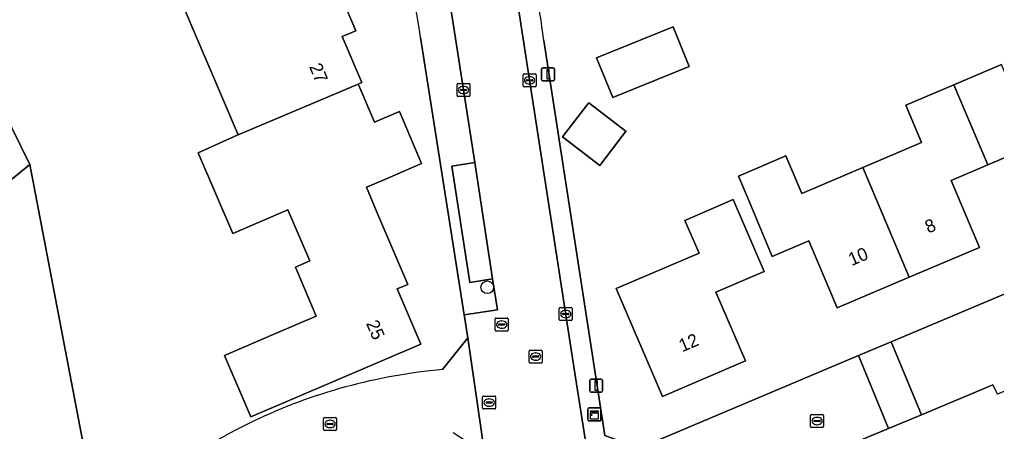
# Model space of a CAD drawing. Extents: x 158472 to 159562, y 388525 to 389606.
# Drawn here: x 158526.8 to 158602.1, y 389028 to 389059.8 of the extents above; entities that cross this region are included whole.
import ezdxf

# ---------------------------------------------------------------- set-up
doc = ezdxf.new("R2010")
doc.units = 0
for name, color, linetype in [('IMGEO_Boom', 7, 'Continuous'), ('IMGEO_Brandkraan', 7, 'Continuous'), ('IMGEO_Erf', 7, 'Continuous'), ('IMGEO_Greppel_droge_sloot', 7, 'Continuous'), ('IMGEO_Groenvoorziening', 7, 'Continuous'), ('IMGEO_Hek', 7, 'Continuous'), ('IMGEO_Kast', 7, 'Continuous'), ('IMGEO_Kolk', 7, 'Continuous'), ('IMGEO_Lichtmast', 7, 'Continuous'), ('IMGEO_Muur', 7, 'Continuous'), ('IMGEO_Pand', 7, 'Continuous'), ('IMGEO_Pand_nummerreeks', 7, 'Continuous'), ('IMGEO_Parkeervlak_open', 7, 'Continuous'), ('IMGEO_Rijbaan_lokaal_open', 7, 'Continuous'), ('IMGEO_Rioolput', 7, 'Continuous'), ('IMGEO_Voetpad_open', 7, 'Continuous')]:
    doc.layers.add(name, color=color, linetype=linetype)

msp = doc.modelspace()

# ---------------------------------------------------------------- linework, layer by layer
at = {"layer": 'IMGEO_Boom'}
msp.add_circle((158562.844, 389039.142), 0.489, dxfattribs=at)
at = {"layer": 'IMGEO_Brandkraan'}
for p, q in [((158562.492, 389029.828), (158562.492, 389030.68)), ((158562.567, 389030.754), (158563.419, 389030.754)), ((158562.751, 389030.248), (158562.751, 389030.26)), ((158563.189, 389030.211), (158562.791, 389030.211)), ((158562.794, 389030.297), (158563.192, 389030.297)), ((158562.98, 389030.534), (158563.005, 389030.534)), ((158563.235, 389030.26), (158563.235, 389030.248)), ((158563.493, 389030.68), (158563.493, 389029.828)), ((158563.419, 389029.754), (158562.567, 389029.754)), ((158563.003, 389029.974), (158562.978, 389029.974))]:
    msp.add_line(p, q, dxfattribs=at)
for points in [[(158562.492, 389029.828), (158562.492, 389030.68)], [(158562.567, 389030.754), (158563.419, 389030.754)], [(158563.493, 389030.68), (158563.493, 389029.828)], [(158563.419, 389029.754), (158562.567, 389029.754)]]:
    msp.add_lwpolyline(points, dxfattribs=at)
for centre, radius, start, end in [((158562.569, 389030.678), 0.0765, 91.55205, 178.44795), ((158562.569, 389030.678), 0.0765, 91.55205, 178.44795), ((158562.791, 389030.257), 0.0403, 85.87752, 175.75265), ((158562.788, 389030.247), 0.0366, 178.93798, 274.71019), ((158563.192, 389030.254), 0.043, 264.86636, 352.45326), ((158563.196, 389030.259), 0.0386, 1.73085, 96.63898), ((158563.417, 389030.678), 0.0765, 1.55205, 88.44795), ((158563.417, 389030.678), 0.0765, 1.55205, 88.44795), ((158562.569, 389029.83), 0.0765, 181.55205, 268.44795), ((158562.569, 389029.83), 0.0765, 181.55205, 268.44795), ((158563.417, 389029.83), 0.0765, 271.55205, 358.44795), ((158563.417, 389029.83), 0.0765, 271.55205, 358.44795)]:
    msp.add_arc(centre, radius, start, end, dxfattribs=at)
for centre, major_axis, ratio, start_param, end_param in [((158562.979, 389030.254), (-0.387, 0.002), 0.722429, 4.712389, 7.853982), ((158563.004, 389030.254), (-0.39, 0.002), 0.717154, 1.570796, 4.712389)]:
    msp.add_ellipse(centre, major_axis=major_axis, ratio=ratio, start_param=start_param, end_param=end_param, dxfattribs=at)
at = {"layer": 'IMGEO_Erf'}
for points in [[(158502.141, 389112.903), (158501.952, 389108.465), (158502.035, 389106.941), (158502.367, 389105.452), (158514.242, 389075.687), (158527.566, 389048.61), (158531.766, 389026.678), (158531.912, 389026.815), (158535.634, 389022.859)], [(158567.204, 389058.167), (158571.923, 389027.713), (158574.563, 389026.742), (158591.467, 389033.868), (158594.001, 389034.936), (158639.056, 389053.929), (158636.872, 389059.257), (158632.833, 389069.111), (158631.513, 389072.331), (158629.191, 389077.996), (158628.001, 389080.824), (158631.763, 389082.407), (158632.597, 389082.746), (158633.427, 389083.084), (158632.28, 389085.631)], [(158549.925, 389065.446), (158552.722, 389058.914), (158551.668, 389058.463), (158553.183, 389054.923), (158552.9, 389054.803), (158552.95, 389054.687), (158554.162, 389051.857), (158556.07, 389052.675), (158557.787, 389048.667), (158554.94, 389047.448), (158553.526, 389046.842), (158554.342, 389044.936), (158556.73, 389039.361), (158555.91, 389039.01), (158557.73, 389034.76), (158544.614, 389029.143), (158542.583, 389033.884), (158546.521, 389035.571), (158549.66, 389036.915), (158548.045, 389040.687), (158549.165, 389041.167), (158547.473, 389045.119), (158543.214, 389043.295), (158540.555, 389049.505), (158543.564, 389050.852), (158543.635, 389050.882), (158539.341, 389060.935)], [(158559.407, 389032.787), (158561.354, 389035.245), (158561.076, 389037.004), (158557.702, 389058.383)], [(158695.038, 389031.866), (158693.979, 389034.415), (158691.297, 389040.872), (158689.958, 389044.098), (158688.082, 389043.319), (158668.118, 389058.458), (158641.722, 389047.425), (158602.187, 389030.899), (158601.851, 389031.612), (158596.34, 389029.317), (158593.802, 389028.26), (158586.677, 389025.294), (158575.064, 389020.458), (158573.349, 389019.024)], [(158604.191, 389049.721), (158601.463, 389048.565), (158598.623, 389047.362), (158600.808, 389042.206), (158595.387, 389039.909), (158589.835, 389037.557), (158587.649, 389042.716), (158584.833, 389041.522), (158582.882, 389046.126), (158582.213, 389047.706), (158585.879, 389049.26), (158587.102, 389046.373), (158591.805, 389048.365), (158596.345, 389050.288), (158595.122, 389053.174), (158598.842, 389054.75), (158602.499, 389056.3)]]:
    msp.add_lwpolyline(points, dxfattribs=at)
for points in [[(158571.283, 389056.835), (158577.19, 389059.217), (158578.429, 389056.144), (158572.522, 389053.762)], [(158573.551, 389051.157), (158573.495, 389051.084), (158571.532, 389048.518), (158568.652, 389050.721), (158570.549, 389053.202), (158570.67, 389053.36)], [(158584.194, 389040.362), (158580.476, 389038.767), (158582.751, 389033.466), (158576.363, 389030.724), (158572.797, 389039.033), (158579.179, 389041.772), (158578.097, 389044.293), (158581.821, 389045.891)]]:
    msp.add_lwpolyline(points, close=True, dxfattribs=at)
for centre, radius, start, end in [((158505.178, 389050.505), 62.498, 7.04204, 22.44265), ((158505.258, 389050.935), 52.97, 8.08322, 18.56797), ((158563.031, 388990.674), 42.269, 94.91889, 115.60393), ((158563.038, 388990.677), 42.269, 115.6136, 130.41517)]:
    msp.add_arc(centre, radius, start, end, dxfattribs=at)
at = {"layer": 'IMGEO_Greppel_droge_sloot'}
msp.add_lwpolyline([(158513.442, 389071.069), (158525.906, 389047.243), (158527.566, 389048.61), (158514.242, 389075.687), (158502.367, 389105.452), (158502.035, 389106.941), (158501.952, 389108.465)], dxfattribs=at)
at = {"layer": 'IMGEO_Groenvoorziening'}
msp.add_lwpolyline([(158527.566, 389048.61), (158525.906, 389047.243), (158510.767, 389041.228), (158507.796, 389039.907), (158521.964, 389021.036), (158524.844, 389017.393), (158526.575, 389013.829), (158529.563, 389016.942), (158530.165, 389017.568), (158531.838, 389019.257), (158535.49, 389022.722), (158531.766, 389026.678)], close=True, dxfattribs=at)
at = {"layer": 'IMGEO_Hek'}
msp.add_lwpolyline([(158527.566, 389048.61), (158531.766, 389026.678)], dxfattribs=at)
at = {"layer": 'IMGEO_Kast'}
for p, q in [((158570.614, 389028.908), (158570.614, 389029.749)), ((158570.614, 389029.749), (158570.614, 389028.908)), ((158570.689, 389029.833), (158571.53, 389029.833)), ((158571.53, 389029.833), (158570.689, 389029.833)), ((158571.614, 389029.758), (158571.614, 389028.917)), ((158571.614, 389028.917), (158571.614, 389029.758)), ((158571.539, 389028.833), (158570.698, 389028.833)), ((158570.698, 389028.833), (158571.539, 389028.833))]:
    msp.add_line(p, q, dxfattribs=at)
for points in [[(158570.809, 389029.623), (158571.409, 389029.623), (158571.409, 389029.538), (158570.809, 389029.538), (158570.809, 389029.623)], [(158570.809, 389029.448), (158571.409, 389029.448), (158571.409, 389028.959), (158570.809, 389028.959), (158570.809, 389029.448)]]:
    msp.add_lwpolyline(points, dxfattribs=at)
msp.add_circle((158570.893, 389029.297), 0.0377, dxfattribs=at)
for centre, start, end in [((158570.692, 389029.755), 92.4484, 184.28452), ((158570.692, 389029.755), 92.4484, 184.28452), ((158571.536, 389029.755), 2.4484, 94.28452), ((158571.536, 389029.755), 2.4484, 94.28452), ((158570.692, 389028.911), 182.4484, 274.28452), ((158570.692, 389028.911), 182.4484, 274.28452), ((158571.536, 389028.911), 272.4484, 4.28452), ((158571.536, 389028.911), 272.4484, 4.28452)]:
    msp.add_arc(centre, 0.0779, start, end, dxfattribs=at)
at = {"layer": 'IMGEO_Kolk'}
for p, q in [((158565.613, 389054.668), (158565.613, 389055.52)), ((158565.688, 389055.594), (158566.54, 389055.594)), ((158565.872, 389055.088), (158565.872, 389055.1)), ((158566.31, 389055.051), (158565.912, 389055.051)), ((158565.915, 389055.137), (158566.313, 389055.137)), ((158566.101, 389055.374), (158566.126, 389055.374)), ((158566.356, 389055.1), (158566.356, 389055.088)), ((158566.614, 389055.52), (158566.614, 389054.668)), ((158560.514, 389053.916), (158560.514, 389054.768)), ((158560.589, 389054.842), (158561.441, 389054.842)), ((158560.773, 389054.336), (158560.773, 389054.348)), ((158561.211, 389054.299), (158560.813, 389054.299)), ((158560.816, 389054.385), (158561.214, 389054.385)), ((158561.002, 389054.622), (158561.027, 389054.622)), ((158561.257, 389054.348), (158561.257, 389054.336)), ((158561.515, 389054.768), (158561.515, 389053.916)), ((158566.54, 389054.594), (158565.688, 389054.594)), ((158566.124, 389054.814), (158566.099, 389054.814)), ((158561.441, 389053.842), (158560.589, 389053.842)), ((158561.025, 389054.062), (158561, 389054.062)), ((158568.401, 389036.646), (158568.401, 389037.498)), ((158568.476, 389037.572), (158569.328, 389037.572)), ((158568.66, 389037.066), (158568.66, 389037.078)), ((158569.098, 389037.029), (158568.7, 389037.029)), ((158568.703, 389037.115), (158569.101, 389037.115)), ((158568.889, 389037.352), (158568.914, 389037.352)), ((158569.144, 389037.078), (158569.144, 389037.066)), ((158569.402, 389037.498), (158569.402, 389036.646)), ((158563.459, 389035.839), (158563.459, 389036.691)), ((158563.534, 389036.765), (158564.386, 389036.765)), ((158563.718, 389036.259), (158563.718, 389036.271)), ((158564.156, 389036.222), (158563.758, 389036.222)), ((158563.761, 389036.308), (158564.159, 389036.308)), ((158563.947, 389036.545), (158563.972, 389036.545)), ((158564.202, 389036.271), (158564.202, 389036.259)), ((158564.46, 389036.691), (158564.46, 389035.839)), ((158569.328, 389036.572), (158568.476, 389036.572)), ((158568.912, 389036.792), (158568.887, 389036.792)), ((158564.386, 389035.765), (158563.534, 389035.765)), ((158563.97, 389035.985), (158563.945, 389035.985)), ((158587.861, 389029.323), (158588.713, 389029.323)), ((158550.223, 389028.179), (158550.223, 389029.031)), ((158550.298, 389029.105), (158551.15, 389029.105)), ((158550.482, 389028.599), (158550.482, 389028.611)), ((158550.525, 389028.648), (158550.923, 389028.648)), ((158550.711, 389028.885), (158550.736, 389028.885)), ((158550.966, 389028.611), (158550.966, 389028.599)), ((158551.224, 389029.031), (158551.224, 389028.179)), ((158587.786, 389028.397), (158587.786, 389029.249)), ((158588.045, 389028.817), (158588.045, 389028.829)), ((158588.483, 389028.78), (158588.085, 389028.78)), ((158588.088, 389028.866), (158588.486, 389028.866)), ((158588.274, 389029.103), (158588.299, 389029.103)), ((158588.529, 389028.829), (158588.529, 389028.817)), ((158588.787, 389029.249), (158588.787, 389028.397)), ((158551.15, 389028.105), (158550.298, 389028.105)), ((158550.92, 389028.562), (158550.522, 389028.562)), ((158550.734, 389028.325), (158550.709, 389028.325)), ((158588.713, 389028.323), (158587.861, 389028.323)), ((158588.297, 389028.543), (158588.272, 389028.543))]:
    msp.add_line(p, q, dxfattribs=at)
for points in [[(158565.613, 389054.668), (158565.613, 389055.52)], [(158565.688, 389055.594), (158566.54, 389055.594)], [(158566.614, 389055.52), (158566.614, 389054.668)], [(158560.514, 389053.916), (158560.514, 389054.768)], [(158560.589, 389054.842), (158561.441, 389054.842)], [(158561.515, 389054.768), (158561.515, 389053.916)], [(158566.54, 389054.594), (158565.688, 389054.594)], [(158561.441, 389053.842), (158560.589, 389053.842)], [(158568.401, 389036.646), (158568.401, 389037.498)], [(158568.476, 389037.572), (158569.328, 389037.572)], [(158569.402, 389037.498), (158569.402, 389036.646)], [(158563.459, 389035.839), (158563.459, 389036.691)], [(158563.534, 389036.765), (158564.386, 389036.765)], [(158564.46, 389036.691), (158564.46, 389035.839)], [(158569.328, 389036.572), (158568.476, 389036.572)], [(158564.386, 389035.765), (158563.534, 389035.765)], [(158587.861, 389029.323), (158588.713, 389029.323)], [(158550.223, 389028.179), (158550.223, 389029.031)], [(158550.298, 389029.105), (158551.15, 389029.105)], [(158551.224, 389029.031), (158551.224, 389028.179)], [(158587.786, 389028.397), (158587.786, 389029.249)], [(158588.787, 389029.249), (158588.787, 389028.397)], [(158551.15, 389028.105), (158550.298, 389028.105)], [(158588.713, 389028.323), (158587.861, 389028.323)]]:
    msp.add_lwpolyline(points, dxfattribs=at)
for centre, radius, start, end in [((158565.69, 389055.518), 0.0765, 91.55205, 178.44795), ((158565.69, 389055.518), 0.0765, 91.55205, 178.44795), ((158565.912, 389055.097), 0.0403, 85.87752, 175.75265), ((158565.909, 389055.087), 0.0366, 178.93798, 274.71019), ((158566.313, 389055.094), 0.043, 264.86636, 352.45326), ((158566.317, 389055.099), 0.0386, 1.73085, 96.63898), ((158566.538, 389055.518), 0.0765, 1.55205, 88.44795), ((158566.538, 389055.518), 0.0765, 1.55205, 88.44795), ((158560.591, 389054.766), 0.0765, 91.55205, 178.44795), ((158560.591, 389054.766), 0.0765, 91.55205, 178.44795), ((158560.813, 389054.345), 0.0403, 85.87752, 175.75265), ((158560.81, 389054.335), 0.0366, 178.93798, 274.71019), ((158561.214, 389054.342), 0.043, 264.86636, 352.45326), ((158561.218, 389054.347), 0.0386, 1.73085, 96.63898), ((158561.439, 389054.766), 0.0765, 1.55205, 88.44795), ((158561.439, 389054.766), 0.0765, 1.55205, 88.44795), ((158565.69, 389054.67), 0.0765, 181.55205, 268.44795), ((158565.69, 389054.67), 0.0765, 181.55205, 268.44795), ((158566.538, 389054.67), 0.0765, 271.55205, 358.44795), ((158566.538, 389054.67), 0.0765, 271.55205, 358.44795), ((158560.591, 389053.918), 0.0765, 181.55205, 268.44795), ((158560.591, 389053.918), 0.0765, 181.55205, 268.44795), ((158561.439, 389053.918), 0.0765, 271.55205, 358.44795), ((158561.439, 389053.918), 0.0765, 271.55205, 358.44795), ((158568.478, 389037.496), 0.0765, 91.55205, 178.44795), ((158568.478, 389037.496), 0.0765, 91.55205, 178.44795), ((158568.7, 389037.075), 0.0403, 85.87752, 175.75265), ((158568.697, 389037.065), 0.0366, 178.93798, 274.71019), ((158569.101, 389037.072), 0.043, 264.86636, 352.45326), ((158569.105, 389037.077), 0.0386, 1.73085, 96.63898), ((158569.326, 389037.496), 0.0765, 1.55205, 88.44795), ((158569.326, 389037.496), 0.0765, 1.55205, 88.44795), ((158563.536, 389036.689), 0.0765, 91.55205, 178.44795), ((158563.536, 389036.689), 0.0765, 91.55205, 178.44795), ((158563.758, 389036.268), 0.0403, 85.87752, 175.75265), ((158563.755, 389036.258), 0.0366, 178.93798, 274.71019), ((158564.159, 389036.265), 0.043, 264.86636, 352.45326), ((158564.163, 389036.27), 0.0386, 1.73085, 96.63898), ((158564.384, 389036.689), 0.0765, 1.55205, 88.44795), ((158564.384, 389036.689), 0.0765, 1.55205, 88.44795), ((158568.478, 389036.648), 0.0765, 181.55205, 268.44795), ((158568.478, 389036.648), 0.0765, 181.55205, 268.44795), ((158569.326, 389036.648), 0.0765, 271.55205, 358.44795), ((158569.326, 389036.648), 0.0765, 271.55205, 358.44795), ((158563.536, 389035.841), 0.0765, 181.55205, 268.44795), ((158563.536, 389035.841), 0.0765, 181.55205, 268.44795), ((158564.384, 389035.841), 0.0765, 271.55205, 358.44795), ((158564.384, 389035.841), 0.0765, 271.55205, 358.44795), ((158587.863, 389029.247), 0.0765, 91.55205, 178.44795), ((158587.863, 389029.247), 0.0765, 91.55205, 178.44795), ((158588.711, 389029.247), 0.0765, 1.55205, 88.44795), ((158588.711, 389029.247), 0.0765, 1.55205, 88.44795), ((158550.3, 389029.029), 0.0765, 91.55205, 178.44795), ((158550.3, 389029.029), 0.0765, 91.55205, 178.44795), ((158550.522, 389028.608), 0.0403, 85.87752, 175.75265), ((158550.519, 389028.598), 0.0366, 178.93798, 274.71019), ((158550.923, 389028.605), 0.043, 264.86636, 352.45326), ((158550.927, 389028.61), 0.0386, 1.73085, 96.63898), ((158551.148, 389029.029), 0.0765, 1.55205, 88.44795), ((158551.148, 389029.029), 0.0765, 1.55205, 88.44795), ((158588.085, 389028.826), 0.0403, 85.87752, 175.75265), ((158588.082, 389028.816), 0.0366, 178.93798, 274.71019), ((158588.486, 389028.823), 0.043, 264.86636, 352.45326), ((158588.49, 389028.828), 0.0386, 1.73085, 96.63898), ((158550.3, 389028.181), 0.0765, 181.55205, 268.44795), ((158550.3, 389028.181), 0.0765, 181.55205, 268.44795), ((158551.148, 389028.181), 0.0765, 271.55205, 358.44795), ((158551.148, 389028.181), 0.0765, 271.55205, 358.44795), ((158587.863, 389028.399), 0.0765, 181.55205, 268.44795), ((158587.863, 389028.399), 0.0765, 181.55205, 268.44795), ((158588.711, 389028.399), 0.0765, 271.55205, 358.44795), ((158588.711, 389028.399), 0.0765, 271.55205, 358.44795)]:
    msp.add_arc(centre, radius, start, end, dxfattribs=at)
for centre, major_axis, ratio, start_param, end_param in [((158566.1, 389055.094), (-0.387, 0.002), 0.722429, 4.712389, 7.853982), ((158566.125, 389055.094), (-0.39, 0.002), 0.717154, 1.570796, 4.712389), ((158561.001, 389054.342), (-0.387, 0.002), 0.722429, 4.712389, 7.853982), ((158561.026, 389054.342), (-0.39, 0.002), 0.717154, 1.570796, 4.712389), ((158568.888, 389037.072), (-0.387, 0.002), 0.722429, 4.712389, 7.853982), ((158568.913, 389037.072), (-0.39, 0.002), 0.717154, 1.570796, 4.712389), ((158563.946, 389036.265), (-0.387, 0.002), 0.722429, 4.712389, 7.853982), ((158563.971, 389036.265), (-0.39, 0.002), 0.717154, 1.570796, 4.712389), ((158550.71, 389028.605), (-0.387, 0.002), 0.722429, 4.712389, 7.853982), ((158550.735, 389028.605), (-0.39, 0.002), 0.717154, 1.570796, 4.712389), ((158588.273, 389028.823), (-0.387, 0.002), 0.722429, 4.712389, 7.853982), ((158588.298, 389028.823), (-0.39, 0.002), 0.717154, 1.570796, 4.712389)]:
    msp.add_ellipse(centre, major_axis=major_axis, ratio=ratio, start_param=start_param, end_param=end_param, dxfattribs=at)
at = {"layer": 'IMGEO_Lichtmast'}
for p, q in [((158567.036, 389055.154), (158567.036, 389055.954)), ((158567.036, 389055.954), (158567.036, 389055.154)), ((158567.136, 389056.054), (158567.926, 389056.054)), ((158567.926, 389056.054), (158567.136, 389056.054)), ((158568.026, 389055.954), (158568.026, 389055.154)), ((158568.026, 389055.154), (158568.026, 389055.954)), ((158567.926, 389055.054), (158567.136, 389055.054)), ((158567.136, 389055.054), (158567.926, 389055.054)), ((158570.753, 389031.164), (158570.753, 389031.964)), ((158570.753, 389031.964), (158570.753, 389031.164)), ((158570.853, 389032.064), (158571.643, 389032.064)), ((158571.643, 389032.064), (158570.853, 389032.064)), ((158571.743, 389031.964), (158571.743, 389031.164)), ((158571.743, 389031.164), (158571.743, 389031.964)), ((158571.643, 389031.064), (158570.853, 389031.064)), ((158570.853, 389031.064), (158571.643, 389031.064))]:
    msp.add_line(p, q, dxfattribs=at)
for points in [[(158567.456, 389055.929), (158567.606, 389055.929), (158567.606, 389055.179), (158567.456, 389055.179), (158567.456, 389055.929)], [(158571.173, 389031.939), (158571.323, 389031.939), (158571.323, 389031.189), (158571.173, 389031.189), (158571.173, 389031.939)]]:
    msp.add_lwpolyline(points, dxfattribs=at)
for centre, start, end in [((158567.136, 389055.954), 90, 180), ((158567.136, 389055.954), 90, 180), ((158567.926, 389055.954), 0, 90), ((158567.926, 389055.954), 360, 90), ((158567.136, 389055.154), 180, 270), ((158567.136, 389055.154), 180, 270), ((158567.926, 389055.154), 270, 0), ((158567.926, 389055.154), 270, 0), ((158570.853, 389031.964), 90, 180), ((158570.853, 389031.964), 90, 180), ((158571.643, 389031.964), 0, 90), ((158571.643, 389031.964), 360, 90), ((158570.853, 389031.164), 180, 270), ((158570.853, 389031.164), 180, 270), ((158571.643, 389031.164), 270, 0), ((158571.643, 389031.164), 270, 0)]:
    msp.add_arc(centre, 0.1, start, end, dxfattribs=at)
at = {"layer": 'IMGEO_Muur'}
for points in [[(158601.851, 389031.612), (158596.34, 389029.317)], [(158596.34, 389029.317), (158593.802, 389028.26)], [(158593.802, 389028.26), (158586.677, 389025.294)]]:
    msp.add_lwpolyline(points, dxfattribs=at)
msp.add_arc((158563.038, 388990.677), 42.269, 115.6136, 130.41517, dxfattribs=at)
at = {"layer": 'IMGEO_Pand'}
for points in [[(158549.925, 389065.446), (158542.488, 389062.32), (158539.341, 389060.935), (158543.635, 389050.882), (158552.9, 389054.803), (158553.183, 389054.923), (158551.668, 389058.463), (158552.722, 389058.914)], [(158571.283, 389056.835), (158572.522, 389053.762), (158578.429, 389056.144), (158577.19, 389059.217)], [(158608.356, 389055.289), (158603.753, 389053.339), (158602.499, 389056.3), (158598.842, 389054.75), (158601.463, 389048.565), (158604.191, 389049.721), (158606.375, 389044.567), (158611.905, 389046.91)], [(158552.9, 389054.803), (158543.635, 389050.882), (158543.564, 389050.852), (158540.555, 389049.505), (158543.214, 389043.295), (158547.473, 389045.119), (158549.165, 389041.167), (158548.045, 389040.687), (158549.66, 389036.915), (158546.521, 389035.571), (158542.583, 389033.884), (158544.614, 389029.143), (158557.73, 389034.76), (158555.91, 389039.01), (158556.73, 389039.361), (158554.342, 389044.936), (158553.526, 389046.842), (158554.94, 389047.448), (158557.787, 389048.667), (158556.07, 389052.675), (158554.162, 389051.857), (158552.95, 389054.687)], [(158591.805, 389048.365), (158595.387, 389039.909), (158600.808, 389042.206), (158598.623, 389047.362), (158601.463, 389048.565), (158598.842, 389054.75), (158595.122, 389053.174), (158596.345, 389050.288)], [(158570.549, 389053.202), (158568.652, 389050.721), (158571.532, 389048.518), (158573.495, 389051.084), (158573.551, 389051.157), (158570.67, 389053.36)], [(158591.805, 389048.365), (158587.102, 389046.373), (158585.879, 389049.26), (158582.213, 389047.706), (158582.882, 389046.126), (158584.833, 389041.522), (158587.649, 389042.716), (158589.835, 389037.557), (158595.387, 389039.909)], [(158576.363, 389030.724), (158582.751, 389033.466), (158580.476, 389038.767), (158584.194, 389040.362), (158581.821, 389045.891), (158578.097, 389044.293), (158579.179, 389041.772), (158572.797, 389039.033)]]:
    msp.add_lwpolyline(points, close=True, dxfattribs=at)
at = {"layer": 'IMGEO_Parkeervlak_open'}
msp.add_lwpolyline([(158561.894, 389048.745), (158560.106, 389048.467), (158561.494, 389039.516), (158563.263, 389039.779)], close=True, dxfattribs=at)
at = {"layer": 'IMGEO_Rijbaan_lokaal_open'}
for points in [[(158559.452, 389063.776), (158559.84, 389061.953), (158561.894, 389048.745), (158563.263, 389039.779), (158563.629, 389037.407), (158561.076, 389037.004), (158561.354, 389035.245), (158562.628, 389026.376), (158562.866, 389024.858), (158564.862, 389025.171), (158565.571, 389024.773), (158565.711, 389023.893), (158566.45, 389019.648), (158566.603, 389019.063), (158566.791, 389018.156)], [(158569.658, 389032.192), (158564.949, 389062.628)], [(158564.949, 389062.628), (158569.658, 389032.192), (158571.227, 389022.248)], [(158571.923, 389027.713), (158567.204, 389058.167)], [(158639.056, 389053.929), (158594.001, 389034.936), (158596.34, 389029.317), (158601.851, 389031.612), (158602.187, 389030.899)], [(158560.226, 389027.942), (158562.628, 389026.376), (158561.354, 389035.245), (158559.407, 389032.787)], [(158573.349, 389019.024), (158575.064, 389020.458), (158586.677, 389025.294), (158593.802, 389028.26), (158591.467, 389033.868), (158574.563, 389026.742), (158571.923, 389027.713)], [(158571.227, 389022.248), (158569.658, 389032.192)]]:
    msp.add_lwpolyline(points, dxfattribs=at)
msp.add_lwpolyline([(158596.34, 389029.317), (158594.001, 389034.936), (158591.467, 389033.868), (158593.802, 389028.26)], close=True, dxfattribs=at)
for centre, radius, start, end in [((158505.178, 389050.505), 62.498, 7.04204, 22.44265), ((158563.031, 388990.674), 42.269, 94.91889, 115.60393), ((158563.038, 388990.677), 42.269, 115.6136, 130.41517)]:
    msp.add_arc(centre, radius, start, end, dxfattribs=at)
at = {"layer": 'IMGEO_Rioolput'}
for p, q in [((158566.076, 389033.372), (158566.076, 389034.224)), ((158566.151, 389034.298), (158567.003, 389034.298)), ((158566.378, 389033.841), (158566.776, 389033.841)), ((158566.564, 389034.078), (158566.589, 389034.078)), ((158567.077, 389034.224), (158567.077, 389033.372)), ((158567.003, 389033.298), (158566.151, 389033.298)), ((158566.335, 389033.792), (158566.335, 389033.804)), ((158566.773, 389033.755), (158566.375, 389033.755)), ((158566.587, 389033.518), (158566.562, 389033.518)), ((158566.819, 389033.804), (158566.819, 389033.792))]:
    msp.add_line(p, q, dxfattribs=at)
for points in [[(158566.076, 389033.372), (158566.076, 389034.224)], [(158566.151, 389034.298), (158567.003, 389034.298)], [(158567.077, 389034.224), (158567.077, 389033.372)], [(158567.003, 389033.298), (158566.151, 389033.298)]]:
    msp.add_lwpolyline(points, dxfattribs=at)
for centre, radius, start, end in [((158566.153, 389034.222), 0.0765, 91.55205, 178.44795), ((158566.153, 389034.222), 0.0765, 91.55205, 178.44795), ((158566.375, 389033.801), 0.0403, 85.87752, 175.75265), ((158566.78, 389033.803), 0.0386, 1.73085, 96.63898), ((158567.001, 389034.222), 0.0765, 1.55205, 88.44795), ((158567.001, 389034.222), 0.0765, 1.55205, 88.44795), ((158566.153, 389033.374), 0.0765, 181.55205, 268.44795), ((158566.153, 389033.374), 0.0765, 181.55205, 268.44795), ((158566.372, 389033.791), 0.0366, 178.93798, 274.71019), ((158566.776, 389033.798), 0.043, 264.86636, 352.45326), ((158567.001, 389033.374), 0.0765, 271.55205, 358.44795), ((158567.001, 389033.374), 0.0765, 271.55205, 358.44795)]:
    msp.add_arc(centre, radius, start, end, dxfattribs=at)
for centre, major_axis, ratio, start_param, end_param in [((158566.563, 389033.798), (-0.387, 0.002), 0.722429, 4.712389, 7.853982), ((158566.588, 389033.798), (-0.39, 0.002), 0.717154, 1.570796, 4.712389)]:
    msp.add_ellipse(centre, major_axis=major_axis, ratio=ratio, start_param=start_param, end_param=end_param, dxfattribs=at)
at = {"layer": 'IMGEO_Voetpad_open'}
msp.add_lwpolyline([(158557.702, 389058.383), (158561.076, 389037.004), (158563.629, 389037.407), (158563.263, 389039.779), (158561.494, 389039.516), (158560.106, 389048.467), (158561.894, 389048.745), (158559.84, 389061.953)], dxfattribs=at)
msp.add_arc((158505.258, 389050.935), 52.97, 8.08322, 18.56797, dxfattribs=at)

# ---------------------------------------------------------------- texts
at = {"layer": 'IMGEO_Pand_nummerreeks'}
for s, rotation, p in [('27', 293.1702, (158549.088, 389056.154)), ('8', 22.96122, (158596.865, 389043.272)), ('10', 22.96122, (158590.954, 389040.767)), ('25', 293.18166, (158553.479, 389036.353)), ('12', 23.23106, (158577.884, 389034.12))]:
    msp.add_text(s, height=1, rotation=rotation, dxfattribs=at).set_placement(p)

doc.saveas('drawing.dxf')
